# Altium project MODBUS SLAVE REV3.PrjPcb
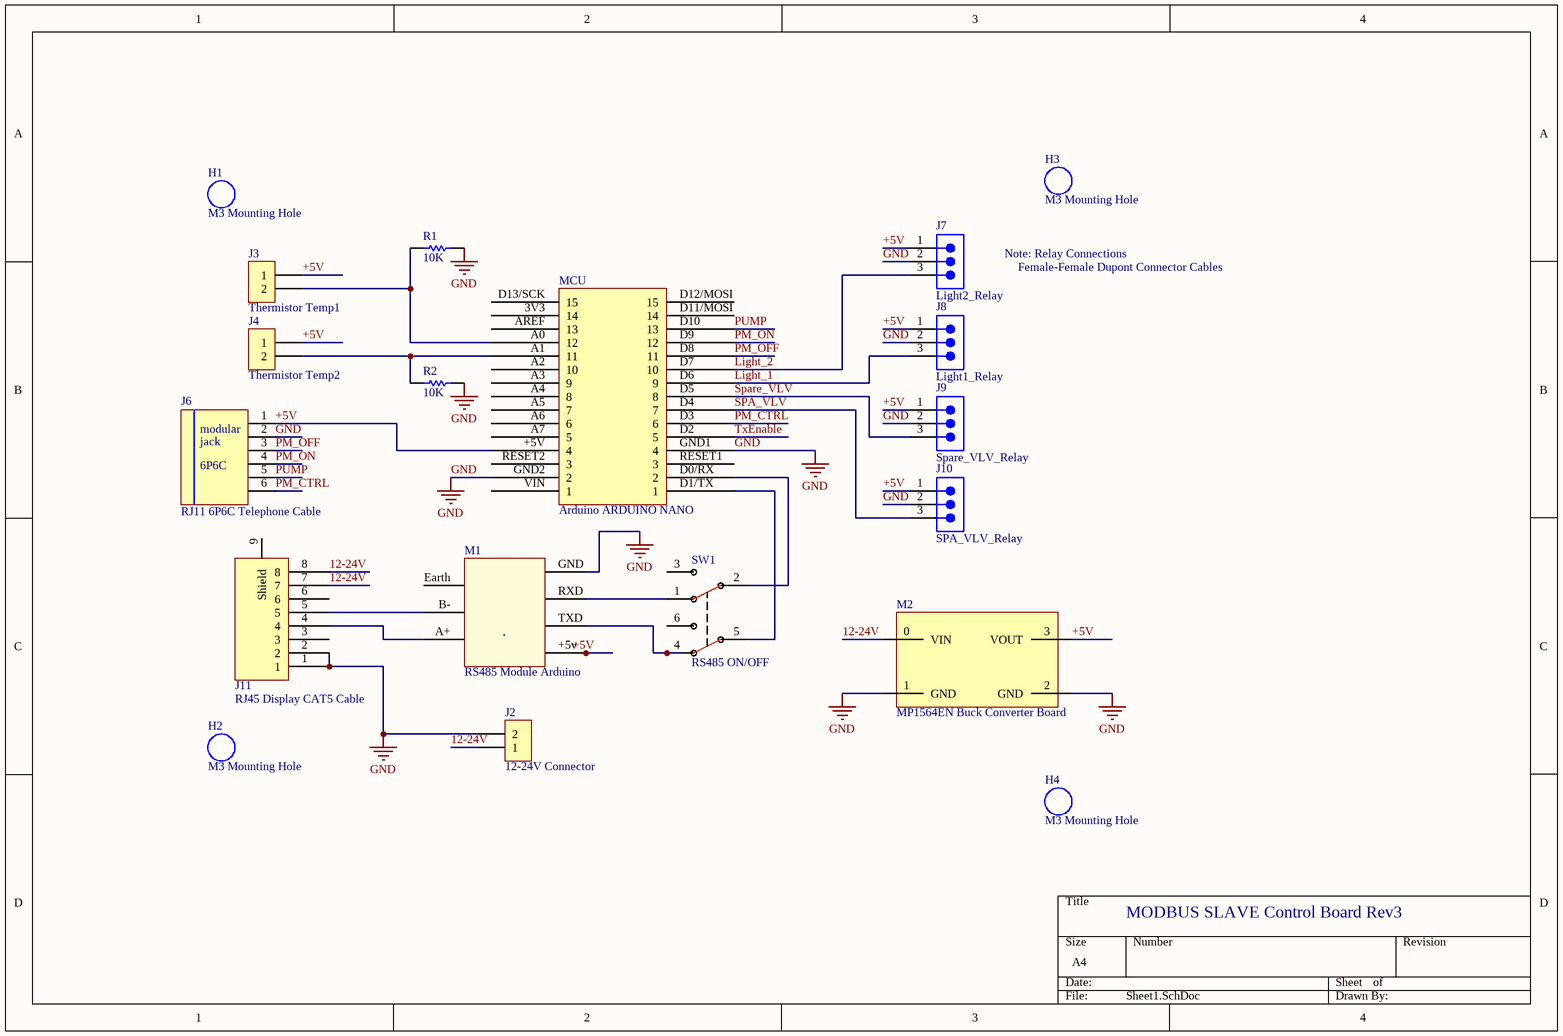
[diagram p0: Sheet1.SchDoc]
1 sheet, 19 parts. Net scope: global (net labels, ports and power ports of the same name join across sheets).

## Sheet Sheet1.SchDoc
size A4

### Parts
H1  M3 Mounting Hole  [PCB-sb9r54v1ukudlsmquqqd-1]
H2  M3 Mounting Hole  [PCB-sb9r54v1ukudlsmquqqd-1]
H3  M3 Mounting Hole  [PCB-sb9r54v1ukudlsmquqqd-1]
H4  M3 Mounting Hole  [PCB-sb9r54v1ukudlsmquqqd-1]
J2  12-24V Connector  [PCB-aknpg75yzj2hq04tmkjt-1]
J3  Thermistor Temp1  [PCB-aknpg75yzj2hq04tmkjt-1]
J4  Thermistor Temp2  [PCB-aknpg75yzj2hq04tmkjt-1]
J6  RJ11 6P6C Telephone Cable  [PCB-617631-1]
J7  Light2_Relay  [PCB-0acd9ij3o7hs0jkl1v86-1]
J8  Light1_Relay  [PCB-0acd9ij3o7hs0jkl1v86-1]
J9  Spare_VLV_Relay  [PCB-0acd9ij3o7hs0jkl1v86-1]
J10  SPA_VLV_Relay  [PCB-0acd9ij3o7hs0jkl1v86-1]
J11  RJ45 Display CAT5 Cable  [PCB-lgdn83qdcnhdjbf49e3k-1]
M1  RS485 Module Arduino  [PCB-fd05ettsbss648nlesx9-1]
M2  MP1564EN Buck Converter Board  [PCB-li055xbo9p6zs65dyiu8-1]
MCU  Arduino ARDUINO NANO  [PCBComponent_1 - duplicate]
R1  10K  [PCB-syetp4j1w4ffj1r241qw-1]
R2  10K  [PCB-syetp4j1w4ffj1r241qw-1]
SW1  RS485 ON/OFF  [PCB-4o0hqz6pdnge3ng8ta2d-1]

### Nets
GND: J2.2 J6.2 J7.2 J8.2 J9.2 J10.2 J11.1 J11.2 M1.GND M2.1(GND) M2.2(GND) MCU.GND1(4) MCU.GND2(2) R1.2 R2.2
12-24V: J2.1 J11.7 J11.8 M2.0(VIN)
+5V: J3.1 J4.1 J6.1 J7.1 J8.1 J9.1 J10.1 M1.+5v(+5V) M2.3(VOUT) MCU.+5V(4)
Light_1: J8.3 MCU.D6(9)
Light_2: J7.3 MCU.D7(10)
PM_CTRL: J6.6 MCU.D3(6)
PM_OFF: J6.3 MCU.D8(11)
PM_ON: J6.4 MCU.D9(12)
PUMP: J6.5 MCU.D10(13)
SPA_VLV: J10.3 MCU.D4(7)
Spare_VLV: J9.3 MCU.D5(8)
TxEnable: MCU.D2(5)
NetJ3_2: J3.2 MCU.A0(12) R1.1
NetJ4_2: J4.2 MCU.A1(11) R2.1
NetJ11_4: J11.4 M1.A+
NetJ11_5: J11.5 M1.B-
NetM1_RXD: M1.RXD SW1.1
NetM1_TXD: M1.TXD SW1.4
NetMCU_D0/RX: MCU.D0/RX(2) SW1.2
NetMCU_D1/TX: MCU.D1/TX(1) SW1.5

Not connected (* = marked no-connect by the designer): J11 3 6 9(Shield); M1 Earth; MCU 3V3(14) A2(10) A3(9) A4(8) A5(7) A6(6) A7(5) AREF(13) D11/MOSI(14) D12/MOSI(15) D13/SCK(15) RESET1(3) RESET2(3) VIN(1); SW1 3 6

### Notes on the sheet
- Note: Relay Connections
- Female-Female Dupont Connector Cables
- MODBUS SLAVE Control Board Rev3

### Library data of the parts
H1-H4 = CMP-2eajnev4pcr11g3c6yc7-1: M3 Mountig Hole
J2-J4 = CMP-0680cf8a1162d947-2: Phoenix 1757242 MSTBA 2.5/ 2-G-5.08 Base Strip/Header 4 Kilo-Volt Surge 320 Volt Rated III/2 12 Amp Green Plug-In; Lead-Free Status: Lead Free; Mounting Angle: 90.0 °; Number of Positions: 2; Voltage Rating (DC): 320.0 V; Gender: Male; Current Rating: 12.0 A; Pin Pitch: 0.00508 m
J6 = CMP-617631-5: Contact Resistance: 0.02 ?; Current Rating: 1.5 A; Gender: Male; Insulation Resistance: 500000000.0 ?; Number of Contacts: 6; Number of Mating Cycles: 500
J7-J10 = CMP-683aa16207d4b7fd-11: 2.54mm (0.1") Pitch SIL Vertical PC Tail Pin Header, 6.1mm mating pin height, gold (hi-temp mould), 3 contacts; Manufacturer Part Number: M20-9990345; Current Rating: 3.00 A; Voltage Rating (AC): 750 V; Gender: Male; Number of Mating Cycles: 300; Number of Contacts: 3; Contact Resistance: 15.0 mΩ
J11 = CMP-95985ce492dd4a5f-11: Socket; RJ45; PIN: 8; Cat: 5e; shielded; gold plated; THT; angled 90°
M1 = CMP-3b2urf91aox2uunr70m7-5: RS485 Module with auto flow control
M2 = CMP-21c200n1kdmmc9b8929b-12: Popular low profile breakout board
MCU = CMP-1f01d29ed047c0c6-2: Arduino Nano
R1 R2 = CMP-0439cd32ffbbdbfe-1: Resistor; Carbon Composition; Res 270 Ohms; Pwr-Rtg 0.25 W; Tol 5%; Axial
SW1 = CMP-0b36c2500016d4f1-7: JS Series DPDT On-On PC Pin Through Hole Subminiature Slide Switch; Lead-Free Status: Lead Free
